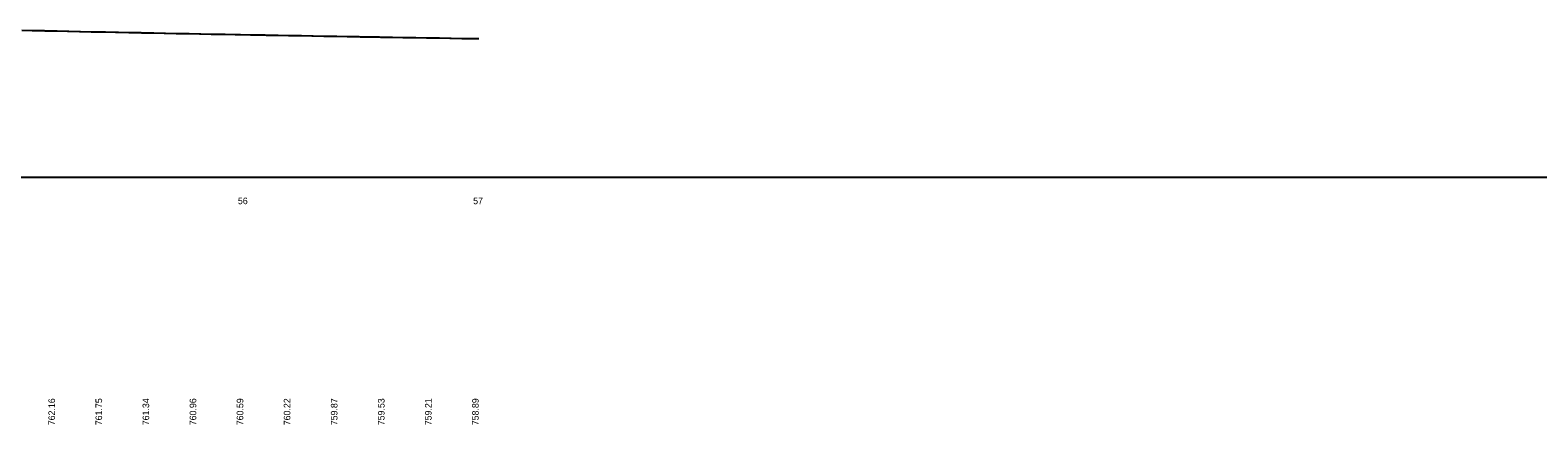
# Model space of a CAD drawing. Extents: x -209 to 3291, y 1080 to 3580.
# Drawn here: x 901 to 1541, y 3225 to 3393 of the extents above; entities that cross this region are included whole.
import ezdxf

# ---------------------------------------------------------------- set-up
doc = ezdxf.new("R2010")
doc.units = 0
for name, color, linetype in [('GK_Cells', 7, 'Continuous'), ('PF_P_Sta_Elev_Text', 7, 'Continuous'), ('PF_X_Ground_Line', 7, 'Continuous'), ('PF_X_Text', 7, 'Continuous')]:
    doc.layers.add(name, color=color, linetype=linetype)

msp = doc.modelspace()

# ---------------------------------------------------------------- linework, layer by layer
at = {"layer": 'GK_Cells'}
msp.add_line((-8.74, 3330.13), (3291.26, 3330.13), dxfattribs=at)
at = {"layer": 'PF_X_Ground_Line'}
for points in [[(897.13, 3392.59), (901.62, 3392.5), (902.13, 3392.49), (906.62, 3392.39), (907.13, 3392.38), (911.62, 3392.28), (912.13, 3392.27), (916.62, 3392.18), (917.13, 3392.17), (921.61, 3392.07), (922.13, 3392.06), (926.61, 3391.96), (927.13, 3391.95), (927.75, 3391.96), (932.11, 3391.86), (932.68, 3391.85), (937.03, 3391.77), (937.68, 3391.74), (938.2, 3391.73), (942.67, 3391.64), (943.21, 3391.63), (947.67, 3391.54), (948.21, 3391.53), (952.67, 3391.45), (953.22, 3391.44), (957.67, 3391.35), (958.22, 3391.34), (962.67, 3391.25), (963.23, 3391.24), (967.66, 3391.16), (968.23, 3391.15), (972.66, 3391.06), (973.24, 3391.05), (977.66, 3390.96), (978.24, 3390.95), (982.66, 3390.87), (983.49, 3390.87), (987.76, 3390.78), (990.09, 3390.74), (994.36, 3390.67), (995.41, 3390.63), (996.01, 3390.62), (1000.41, 3390.55), (1001, 3390.53), (1005.41, 3390.46), (1006, 3390.45), (1010.41, 3390.37), (1011, 3390.36), (1015.41, 3390.28), (1015.99, 3390.27), (1020.41, 3390.19), (1020.99, 3390.18), (1025.41, 3390.1), (1025.99, 3390.09), (1030.41, 3390.02), (1030.98, 3390), (1035.41, 3389.93), (1035.98, 3389.92), (1040.41, 3389.84), (1040.94, 3389.83), (1044.58, 3389.77), (1049.03, 3389.7), (1049.58, 3389.69), (1054.03, 3389.62), (1054.58, 3389.61), (1059.04, 3389.54), (1059.58, 3389.53), (1064.05, 3389.46), (1064.58, 3389.45), (1069.06, 3389.37), (1069.58, 3389.37), (1074.06, 3389.29), (1074.58, 3389.29), (1079.07, 3389.21), (1079.57, 3389.21), (1084.08, 3389.13), (1084.57, 3389.12), (1089.09, 3389.05)], [(1089.09, 3389.05), (1089.57, 3389.04), (1089.93, 3389.04), (1091.26, 3389.02)]]:
    msp.add_lwpolyline(points, dxfattribs=at)

# ---------------------------------------------------------------- texts
at = {"layer": 'PF_P_Sta_Elev_Text'}
for s, p in [('56', (988.96, 3318.73)), ('57', (1088.91, 3318.73))]:
    msp.add_text(s, height=2.8, dxfattribs=at).set_placement(p)
at = {"layer": 'PF_X_Text'}
for s, p in [('762.16', (911.26, 3224.88)), ('761.75', (931.26, 3224.88)), ('761.34', (951.26, 3224.88)), ('760.96', (971.26, 3224.88)), ('760.59', (991.26, 3224.88)), ('760.22', (1011.26, 3224.88)), ('759.87', (1031.26, 3224.88)), ('759.53', (1051.26, 3224.88)), ('759.21', (1071.26, 3224.88)), ('758.89', (1091.26, 3224.88))]:
    msp.add_text(s, height=2.8, rotation=90, dxfattribs=at).set_placement(p)

doc.saveas('drawing.dxf')
